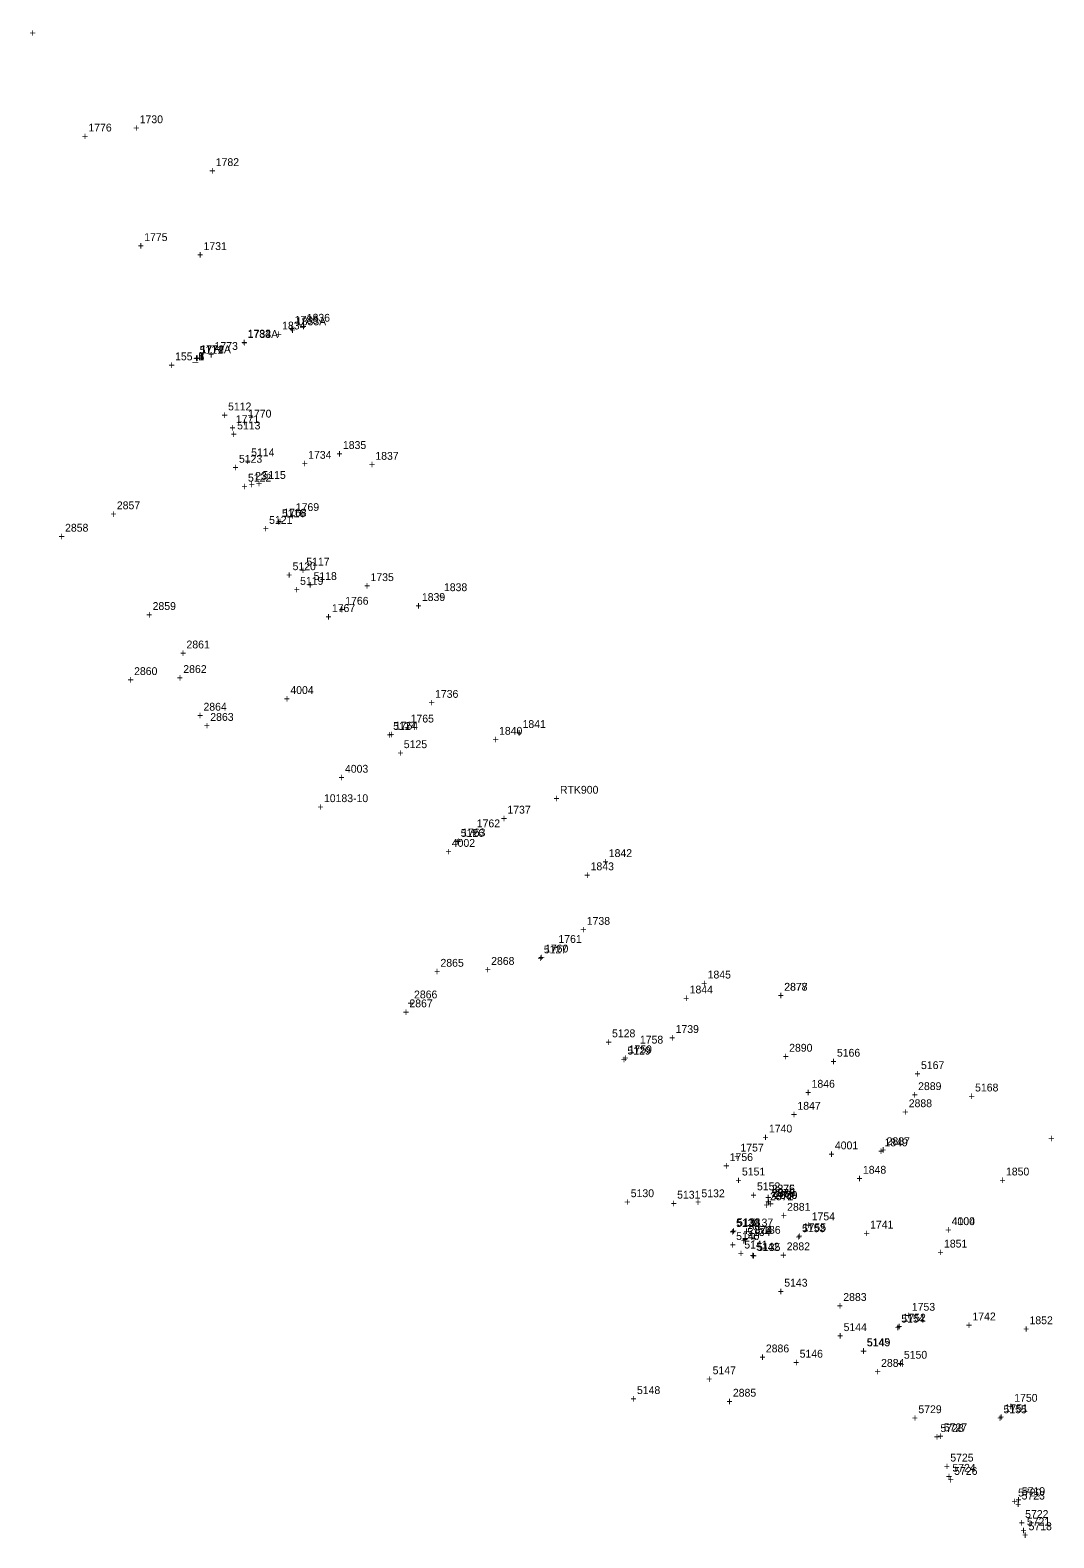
# Model space of a CAD drawing. Extents: x 1036751 to 1042192, y 772604 to 785439.
# Drawn here: x 1039926.5 to 1040253.4, y 775322.9 to 775804.1 of the extents above; entities that cross this region are included whole.
import ezdxf

# ---------------------------------------------------------------- set-up
doc = ezdxf.new("R2010")
doc.units = 0
for name, color, linetype in [('S_Bridge_Centerline', 7, 'Continuous'), ('S_Bridge_Deck', 7, 'Continuous'), ('S_Buildings', 7, 'Continuous'), ('S_Buildings_SillElevation', 7, 'Continuous'), ('S_Control_Geodetic_ControlPoint', 7, 'Continuous'), ('S_Control_Temp_Traverse', 7, 'Continuous'), ('S_Curb_Type_3', 7, 'Continuous'), ('S_Drainage_CB', 7, 'Continuous'), ('S_Drainage_Culvert_Top', 7, 'Continuous'), ('S_Drainage_Invert', 7, 'Continuous'), ('S_Drainage_Sump', 7, 'Continuous'), ('S_Fencing_Page', 7, 'Continuous'), ('S_Ground_Elevation', 7, 'Continuous'), ('S_Ground_LevelString', 7, 'Continuous'), ('S_Misc_MiscItems', 7, 'Continuous'), ('S_Property_ConcPad', 7, 'Continuous'), ('S_Property_Well_Top', 7, 'Continuous'), ('S_Roadway_Centerline', 7, 'Continuous'), ('S_Roadway_Edge_Pavement', 7, 'Continuous'), ('S_Roadway_Edge_TW', 7, 'Continuous'), ('S_Traffic_Sign_SinglePost', 7, 'Continuous'), ('S_Trees_Conifer_Pay', 7, 'Continuous'), ('S_Utilities_GuyWire3', 7, 'Continuous'), ('S_Utilities_Pole_Power', 7, 'Continuous'), ('S_Utilities_UG_Water_Line', 7, 'Continuous')]:
    doc.layers.add(name, color=color, linetype=linetype)

msp = doc.modelspace()

# ---------------------------------------------------------------- texts
at = {"layer": 'S_Bridge_Centerline'}
for s, p in [('+', (1039959.43, 775771.62)), ('1730', (1039961.49, 775774.37)), ('1731', (1039981.87, 775733.9)), ('+', (1039979.81, 775731.15)), ('1732', (1039995.94, 775705.98)), ('+', (1039993.88, 775703.23))]:
    msp.add_text(s, height=2.5, dxfattribs=at).set_placement(p)
at = {"layer": 'S_Bridge_Deck'}
for s, p in [('+', (1039926.34, 775801.97)), ('1776', (1039945.11, 775771.73)), ('+', (1039943.05, 775768.98)), ('+', (1039983.71, 775757.95)), ('1782', (1039985.78, 775760.7)), ('+', (1039960.87, 775734.02)), ('1775', (1039962.93, 775736.77)), ('1783', (1040011.01, 775710.39)), ('1784', (1039995.93, 775705.97)), ('+', (1040008.95, 775707.64)), ('1774', (1039980.82, 775701)), ('+', (1039993.87, 775703.22)), ('+', (1039978.76, 775698.25))]:
    msp.add_text(s, height=2.5, dxfattribs=at).set_placement(p)
at = {"layer": 'S_Buildings'}
for s, p in [('2862', (1039975.41, 775598.9)), ('+', (1039973.35, 775596.15)), ('2863', (1039984.03, 775583.63)), ('+', (1039981.97, 775580.88))]:
    msp.add_text(s, height=2.5, dxfattribs=at).set_placement(p)
at = {"layer": 'S_Buildings_SillElevation'}
for s, p in [('+', (1039979.79, 775584.14)), ('2864', (1039981.85, 775586.89))]:
    msp.add_text(s, height=2.5, dxfattribs=at).set_placement(p)
at = {"layer": 'S_Control_Geodetic_ControlPoint'}
for s, p in [('23', (1039998.35, 775660.57)), ('23', (1039998.35, 775660.57)), ('23', (1039998.35, 775660.57)), ('23', (1039998.35, 775660.57)), ('23', (1039998.35, 775660.57)), ('23', (1039998.35, 775660.57)), ('23', (1039998.35, 775660.57)), ('23', (1039998.35, 775660.57)), ('23', (1039998.35, 775660.57)), ('23', (1039998.35, 775660.57)), ('23', (1039998.35, 775660.57)), ('23', (1039998.35, 775660.57)), ('+', (1039996.29, 775657.82)), ('+', (1039996.29, 775657.82)), ('+', (1039996.29, 775657.82)), ('+', (1039996.29, 775657.82)), ('+', (1039996.29, 775657.82)), ('+', (1039996.29, 775657.82)), ('+', (1039996.29, 775657.82)), ('+', (1039996.29, 775657.82)), ('+', (1039996.29, 775657.82)), ('+', (1039996.29, 775657.82)), ('+', (1039996.29, 775657.82)), ('+', (1039996.29, 775657.82)), ('10183-10', (1040020.32, 775557.69)), ('10183-10', (1040020.32, 775557.69)), ('10183-10', (1040020.32, 775557.69)), ('+', (1040018.26, 775554.94)), ('+', (1040018.26, 775554.94)), ('+', (1040018.26, 775554.94))]:
    msp.add_text(s, height=2.5, dxfattribs=at).set_placement(p)
at = {"layer": 'S_Control_Temp_Traverse'}
for s, p in [('+', (1039970.72, 775695.95)), ('+', (1039970.72, 775695.95)), ('+', (1039970.71, 775695.95)), ('+', (1039970.71, 775695.95)), ('+', (1039970.71, 775695.95)), ('+', (1039970.71, 775695.95)), ('+', (1039970.71, 775695.95)), ('155_3', (1039972.78, 775698.7)), ('155_2', (1039972.78, 775698.7)), ('155', (1039972.78, 775698.7)), ('155', (1039972.78, 775698.7)), ('155_1', (1039972.78, 775698.7)), ('155_5', (1039972.78, 775698.7)), ('155_4', (1039972.78, 775698.7)), ('RTK900', (1040095.69, 775560.38)), ('RTK900', (1040095.69, 775560.38)), ('RTK900', (1040095.69, 775560.38)), ('+', (1040093.63, 775557.63)), ('+', (1040093.63, 775557.63)), ('+', (1040093.63, 775557.63))]:
    msp.add_text(s, height=2.5, dxfattribs=at).set_placement(p)
at = {"layer": 'S_Curb_Type_3'}
for s, p in [('5111', (1039980.63, 775700.79)), ('+', (1039978.57, 775698.04)), ('5112', (1039989.71, 775682.72)), ('+', (1039987.65, 775679.97)), ('5113', (1039992.6, 775676.65)), ('+', (1039990.54, 775673.9)), ('5123', (1039993.18, 775666.01)), ('5114', (1039997.07, 775668.06)), ('+', (1039991.12, 775663.26)), ('+', (1039995.01, 775665.31)), ('5115', (1040000.69, 775660.86)), ('+', (1039994, 775657.24)), ('5122', (1039996.06, 775659.99)), ('+', (1039998.62, 775658.11)), ('5121', (1040002.81, 775646.5)), ('5116', (1040006.91, 775648.63)), ('+', (1040000.75, 775643.75)), ('+', (1040004.85, 775645.88)), ('5120', (1040010.3, 775631.72)), ('5117', (1040014.68, 775633.2)), ('+', (1040008.24, 775628.97)), ('+', (1040012.62, 775630.45)), ('5119', (1040012.71, 775627.05)), ('5118', (1040017, 775628.58)), ('+', (1040010.65, 775624.3)), ('+', (1040014.94, 775625.83)), ('5124', (1040042.42, 775580.73)), ('+', (1040040.35, 775577.98)), ('5125', (1040045.82, 775574.92)), ('+', (1040043.76, 775572.17)), ('5126', (1040064, 775546.61)), ('+', (1040061.94, 775543.86)), ('5127', (1040090.52, 775509.42)), ('+', (1040088.46, 775506.67)), ('5128', (1040112.31, 775482.64)), ('+', (1040110.25, 775479.89)), ('+', (1040115.16, 775474.37)), ('5129', (1040117.22, 775477.12)), ('+', (1040151.72, 775435.78)), ('5151', (1040153.78, 775438.53)), ('+', (1040156.53, 775431.06)), ('5152', (1040158.59, 775433.81)), ('5153', (1040172.98, 775420.44)), ('+', (1040170.92, 775417.69)), ('5154', (1040204.66, 775391.59)), ('+', (1040202.6, 775388.84)), ('5155', (1040237.3, 775362.64)), ('+', (1040235.24, 775359.89))]:
    msp.add_text(s, height=2.5, dxfattribs=at).set_placement(p)
at = {"layer": 'S_Drainage_CB'}
for s, p in [('2869', (1040163.38, 775431.62)), ('+', (1040161.32, 775428.87))]:
    msp.add_text(s, height=2.5, dxfattribs=at).set_placement(p)
at = {"layer": 'S_Drainage_Culvert_Top'}
for s, p in [('2877', (1040167.33, 775497.49)), ('+', (1040165.27, 775494.74)), ('+', (1040161.23, 775430.33)), ('2872', (1040162.74, 775430.63)), ('2876', (1040163.29, 775433.08)), ('2880', (1040164.07, 775431.03)), ('+', (1040160.68, 775427.88)), ('+', (1040162, 775428.28)), ('2881', (1040168.23, 775427.27)), ('2873', (1040155.92, 775419.85)), ('+', (1040166.17, 775424.52)), ('+', (1040153.85, 775417.1))]:
    msp.add_text(s, height=2.5, dxfattribs=at).set_placement(p)
at = {"layer": 'S_Drainage_Invert'}
for s, p in [('2878', (1040167.27, 775497.5)), ('+', (1040165.21, 775494.75)), ('+', (1040161.19, 775430.31)), ('2871', (1040162.77, 775430.66)), ('2875', (1040163.25, 775433.06)), ('2879', (1040164.01, 775431.09)), ('+', (1040160.71, 775427.91)), ('+', (1040161.95, 775428.34)), ('2874', (1040155.95, 775419.94)), ('+', (1040153.89, 775417.19))]:
    msp.add_text(s, height=2.5, dxfattribs=at).set_placement(p)
at = {"layer": 'S_Drainage_Sump'}
for s, p in [('2870', (1040163.23, 775431.72)), ('+', (1040161.17, 775428.97))]:
    msp.add_text(s, height=2.5, dxfattribs=at).set_placement(p)
at = {"layer": 'S_Fencing_Page'}
for s, p in [('2884', (1040198.22, 775377.45)), ('+', (1040196.16, 775374.7)), ('2885', (1040150.9, 775367.94)), ('+', (1040148.84, 775365.19))]:
    msp.add_text(s, height=2.5, dxfattribs=at).set_placement(p)
at = {"layer": 'S_Ground_Elevation'}
for s, p in [('+', (1040182.06, 775473.7)), ('5166', (1040184.12, 775476.45)), ('+', (1040208.91, 775469.74)), ('5167', (1040210.97, 775472.49)), ('5168', (1040228.24, 775465.35)), ('+', (1040226.18, 775462.6)), ('+', (1040251.6, 775449.15)), ('5130', (1040118.29, 775431.61)), ('5131', (1040133.09, 775431.14)), ('5132', (1040140.86, 775431.58)), ('+', (1040116.23, 775428.86)), ('+', (1040131.03, 775428.39)), ('+', (1040138.8, 775428.83)), ('5139', (1040151.91, 775422.09)), ('5133', (1040152.17, 775422.35)), ('5138', (1040152.26, 775422.36)), ('5137', (1040156.34, 775422.27)), ('5136', (1040158.71, 775419.92)), ('+', (1040149.85, 775419.34)), ('+', (1040150.11, 775419.6)), ('+', (1040150.2, 775419.61)), ('5140', (1040151.94, 775417.93)), ('+', (1040153.41, 775416.49)), ('+', (1040154.28, 775419.52)), ('5141', (1040154.55, 775415.22)), ('5134', (1040155.47, 775419.24)), ('+', (1040156.65, 775417.17)), ('+', (1040149.88, 775415.18)), ('+', (1040152.49, 775412.47)), ('+', (1040156.28, 775411.79)), ('+', (1040156.57, 775411.66)), ('5142', (1040158.34, 775414.54)), ('5135', (1040158.63, 775414.41)), ('5143', (1040167.3, 775403.05)), ('+', (1040165.24, 775400.3)), ('5144', (1040186.25, 775388.87)), ('+', (1040184.19, 775386.12)), ('5145', (1040193.63, 775384.07)), ('5149', (1040193.75, 775383.99)), ('+', (1040170.16, 775377.64)), ('5146', (1040172.22, 775380.39)), ('+', (1040191.57, 775381.32)), ('+', (1040191.69, 775381.24)), ('+', (1040203.44, 775377.3)), ('5150', (1040205.5, 775380.05)), ('+', (1040142.38, 775372.35)), ('5147', (1040144.44, 775375.1)), ('5148', (1040120.27, 775368.77)), ('+', (1040118.21, 775366.02))]:
    msp.add_text(s, height=2.5, dxfattribs=at).set_placement(p)
at = {"layer": 'S_Ground_LevelString'}
for s, p in [('1833A', (1040011.35, 775709.89)), ('1733A', (1039996.02, 775705.82)), ('+', (1040009.29, 775707.14)), ('1772A', (1039980.95, 775700.93)), ('+', (1039993.96, 775703.07)), ('+', (1039978.89, 775698.18))]:
    msp.add_text(s, height=2.5, dxfattribs=at).set_placement(p)
at = {"layer": 'S_Misc_MiscItems'}
for s, p in [('5729', (1040210.13, 775362.67)), ('+', (1040208.06, 775359.92)), ('+', (1040218.26, 775344.49)), ('5725', (1040220.32, 775347.24)), ('5724', (1040220.99, 775343.98)), ('+', (1040218.93, 775341.23)), ('5723', (1040243.09, 775335.11)), ('+', (1040241.03, 775332.36)), ('5722', (1040244.22, 775329.23)), ('+', (1040242.16, 775326.48)), ('+', (1040242.72, 775324.05)), ('5721', (1040244.78, 775326.8))]:
    msp.add_text(s, height=2.5, dxfattribs=at).set_placement(p)
at = {"layer": 'S_Property_ConcPad'}
for s, p in [('+', (1040215.1, 775353.9)), ('+', (1040216.19, 775354.14)), ('5728', (1040217.16, 775356.65)), ('5727', (1040218.25, 775356.89)), ('5726', (1040221.55, 775342.97)), ('+', (1040219.49, 775340.22)), ('+', (1040241.11, 775333.8)), ('5720', (1040241.96, 775336.08)), ('5719', (1040243.17, 775336.55)), ('+', (1040239.9, 775333.33)), ('5718', (1040245.32, 775325.31)), ('+', (1040243.26, 775322.56))]:
    msp.add_text(s, height=2.5, dxfattribs=at).set_placement(p)
at = {"layer": 'S_Property_Well_Top'}
for s, p in [('2886', (1040161.43, 775382.07)), ('+', (1040159.37, 775379.32))]:
    msp.add_text(s, height=2.5, dxfattribs=at).set_placement(p)
at = {"layer": 'S_Roadway_Centerline'}
for s, p in [('1733', (1039996.02, 775705.82)), ('+', (1039993.96, 775703.07)), ('1734', (1040015.28, 775667.27)), ('+', (1040013.22, 775664.52)), ('1735', (1040035.19, 775628.24)), ('+', (1040033.13, 775625.49)), ('1736', (1040055.8, 775590.98)), ('+', (1040053.74, 775588.23)), ('+', (1040076.84, 775551.27)), ('1737', (1040078.9, 775554.02)), ('1738', (1040104.24, 775518.53)), ('+', (1040102.18, 775515.78)), ('1739', (1040132.61, 775484.02)), ('+', (1040130.55, 775481.27)), ('+', (1040160.34, 775449.5)), ('1740', (1040162.41, 775452.25)), ('1741', (1040194.7, 775421.6)), ('+', (1040192.64, 775418.85)), ('1742', (1040227.39, 775392.29)), ('+', (1040225.33, 775389.54))]:
    msp.add_text(s, height=2.5, dxfattribs=at).set_placement(p)
at = {"layer": 'S_Roadway_Edge_Pavement'}
for s, p in [('1833', (1040011.35, 775709.89)), ('1836', (1040014.82, 775711.03)), ('+', (1040009.29, 775707.14)), ('+', (1040012.76, 775708.28)), ('1772', (1039980.95, 775700.93)), ('+', (1039978.89, 775698.18)), ('+', (1039990.12, 775675.92)), ('1771', (1039992.18, 775678.67)), ('1837', (1040036.74, 775666.95)), ('+', (1040034.68, 775664.2)), ('1768', (1040007.35, 775648.83)), ('+', (1040005.29, 775646.08)), ('1838', (1040058.64, 775625.02)), ('1767', (1040022.85, 775618.35)), ('+', (1040056.58, 775622.27)), ('+', (1040020.79, 775615.6)), ('1764', (1040042.95, 775580.85)), ('1841', (1040083.74, 775581.35)), ('+', (1040040.89, 775578.1)), ('+', (1040081.68, 775578.6)), ('1763', (1040064.44, 775546.76)), ('+', (1040062.38, 775544.01)), ('1842', (1040111.27, 775540.16)), ('+', (1040109.21, 775537.41)), ('+', (1040088.86, 775506.96)), ('1760', (1040090.92, 775509.71)), ('+', (1040140.78, 775498.65)), ('1845', (1040142.84, 775501.4)), ('1759', (1040117.63, 775477.54)), ('+', (1040115.57, 775474.79)), ('+', (1040173.97, 775463.8)), ('1846', (1040176.03, 775466.55)), ('+', (1040197.25, 775445.09)), ('1849', (1040199.31, 775447.84)), ('+', (1040147.82, 775440.39)), ('1756', (1040149.88, 775443.14)), ('+', (1040236.04, 775435.79)), ('1850', (1040238.1, 775438.54)), ('1755', (1040173.22, 775420.74)), ('+', (1040171.16, 775417.99)), ('1752', (1040205.07, 775391.88)), ('+', (1040203.01, 775389.13)), ('1751', (1040237.65, 775362.99)), ('+', (1040235.58, 775360.24))]:
    msp.add_text(s, height=2.5, dxfattribs=at).set_placement(p)
at = {"layer": 'S_Roadway_Edge_TW'}
for s, p in [('1834', (1040006.97, 775708.55)), ('+', (1040004.91, 775705.8)), ('1773', (1039985.4, 775702.02)), ('+', (1039983.34, 775699.27)), ('1770', (1039996.12, 775680.43)), ('+', (1039994.06, 775677.68)), ('1835', (1040026.37, 775670.41)), ('+', (1040024.31, 775667.66)), ('+', (1040009.28, 775647.85)), ('1769', (1040011.34, 775650.6)), ('1839', (1040051.59, 775621.88)), ('+', (1040025.06, 775617.94)), ('1766', (1040027.12, 775620.69)), ('+', (1040049.53, 775619.13)), ('+', (1040045.94, 775580.35)), ('1765', (1040048, 775583.1)), ('1840', (1040076.23, 775579.19)), ('+', (1040074.17, 775576.44)), ('+', (1040067.06, 775546.91)), ('1762', (1040069.12, 775549.66)), ('1843', (1040105.48, 775535.94)), ('+', (1040103.41, 775533.19)), ('1761', (1040095.19, 775512.77)), ('+', (1040093.13, 775510.02)), ('+', (1040135.04, 775493.88)), ('1844', (1040137.1, 775496.63)), ('1758', (1040121.21, 775480.63)), ('+', (1040119.15, 775477.88)), ('1847', (1040171.5, 775459.52)), ('+', (1040169.44, 775456.77)), ('1757', (1040153.32, 775446.18)), ('+', (1040151.26, 775443.43)), ('1848', (1040192.42, 775439.1)), ('+', (1040190.36, 775436.35)), ('+', (1040174.01, 775421.48)), ('1754', (1040176.07, 775424.23)), ('1851', (1040218.31, 775415.53)), ('+', (1040216.25, 775412.78)), ('+', (1040205.98, 775392.61)), ('1753', (1040208.04, 775395.36)), ('1852', (1040245.62, 775391.07)), ('+', (1040243.56, 775388.32)), ('+', (1040238.68, 775363.56)), ('1750', (1040240.74, 775366.31))]:
    msp.add_text(s, height=2.5, dxfattribs=at).set_placement(p)
at = {"layer": 'S_Traffic_Sign_SinglePost'}
for s, p in [('+', (1040071.65, 775503)), ('2868', (1040073.71, 775505.75)), ('2890', (1040168.87, 775478.04)), ('+', (1040166.81, 775475.29))]:
    msp.add_text(s, height=2.5, dxfattribs=at).set_placement(p)
at = {"layer": 'S_Trees_Conifer_Pay'}
for s, p in [('+', (1040166.02, 775411.91)), ('2882', (1040168.09, 775414.66)), ('2883', (1040186.15, 775398.49)), ('+', (1040184.09, 775395.74))]:
    msp.add_text(s, height=2.5, dxfattribs=at).set_placement(p)
at = {"layer": 'S_Utilities_GuyWire3'}
for s, p in [('2858', (1039937.66, 775644.01)), ('+', (1039935.6, 775641.26)), ('2859', (1039965.62, 775619.02)), ('+', (1039963.56, 775616.27)), ('2860', (1039959.7, 775598.25)), ('+', (1039957.64, 775595.5)), ('2867', (1040047.61, 775492.21)), ('2866', (1040049.09, 775495.05)), ('+', (1040045.55, 775489.46)), ('+', (1040047.03, 775492.3)), ('2889', (1040210.05, 775465.79)), ('2888', (1040207.05, 775460.33)), ('+', (1040207.99, 775463.04)), ('+', (1040204.98, 775457.58))]:
    msp.add_text(s, height=2.5, dxfattribs=at).set_placement(p)
at = {"layer": 'S_Utilities_Pole_Power'}
for s, p in [('2857', (1039954.19, 775651.16)), ('+', (1039952.13, 775648.41)), ('+', (1039974.37, 775604)), ('2861', (1039976.43, 775606.75)), ('+', (1040055.47, 775502.4)), ('2865', (1040057.53, 775505.15)), ('+', (1040197.92, 775445.47)), ('2887', (1040199.98, 775448.22))]:
    msp.add_text(s, height=2.5, dxfattribs=at).set_placement(p)
at = {"layer": 'S_Utilities_UG_Water_Line'}
for s, p in [('+', (1040007.53, 775589.45)), ('4004', (1040009.59, 775592.2)), ('4003', (1040027.03, 775567.08)), ('+', (1040024.97, 775564.33)), ('+', (1040059.08, 775540.66)), ('4002', (1040061.14, 775543.41)), ('4001', (1040183.47, 775446.89)), ('+', (1040181.41, 775444.14)), ('4000', (1040220.74, 775422.69)), ('4104', (1040220.79, 775422.69)), ('+', (1040218.68, 775419.94)), ('+', (1040218.72, 775419.94))]:
    msp.add_text(s, height=2.5, dxfattribs=at).set_placement(p)

doc.saveas('drawing.dxf')
